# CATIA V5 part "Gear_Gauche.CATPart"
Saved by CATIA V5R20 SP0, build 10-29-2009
Part number: Pièce1
Bounding box of the stored display mesh (mm): x -14.825 to 18.25, y -12.496 to 12.496, z -18 to 15.7
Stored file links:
  C:\Users\Admin\Desktop\Gear Gauche.CATPart
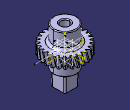
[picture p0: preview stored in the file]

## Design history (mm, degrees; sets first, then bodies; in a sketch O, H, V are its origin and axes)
Body1 (main body)
  Sketch1 on xy-plane, origin (0, 0, 0), H (1, 0, 0), V (0, 1, 0)
  Sketch2 on zx-plane, origin (0, 0, 0), H (-1, 0, 0), V (0, 0, 1)
    line L1 (0, 0) -> (1.2812, 4.4681)
    angle L1 V = 16
  Sketch3 on xy-plane, origin (0, 0, 0), H (1, 0, 0), V (0, 1, 0)
    circle A1 centre (0, 0) radius 10.75
    radius A1 = 10.75
  Pad1: profile Sketch3, direction (0, 0, 1), length 6.1
  Plane1: type Offset, RefPlane xy-plane, Offset 3.05
  Sketch4 on Plane1, origin (0, 0, 3.05), H (1, 0, 0), V (0, 1, 0)
    line L1 (0, 4.9753) -> (0, -6.0734)
    point P1 (0, 4.9753)
    line L2 (-14.8253, 0) -> (18.2495, 0)
    point P3 (-14.8253, 0)
    coincidence: P1 V, P3 H
    vertical: L1 V
    horizontal: L2 H
  Plane2: type Angle, RefPlane Plane1, Direction Sketch4.L2, Angle 15.6
  Sketch5 on Plane2, origin (0, -0.8097, 2.8239), H (1, 0, 0), V (0, 0.9632, 0.2689)
    point P1 (0, -9.9093)
    construction circle A1 centre (-0.013, 0.8407) radius 10.75
    construction line L1 through (0, 0.8407) direction (0, -1)
    construction line L2 through (0, 0.8407) direction (1, 0)
    point P2 (12.3622, 0.8407)
    axis line L3 (12.3622, 0.8407) -> (-13.4567, 0.8407)
    line L4 (12.437, 1.2157) -> (12.437, 0.4657)
    point P3 (10.737, 0.8407)
    point P4 (12.437, 1.2157)
    spline S1 through (12.437, 0.4657) (11.9519, 0.1717) (11.214, -0.0548) (10.6904, -0.1593)
    spline S2 through (12.437, 1.2157) (11.9519, 1.5097) (11.214, 1.7361) (10.6904, 1.8407)
    point P7 (10.6904, 1.8407)
    construction arc A2 centre (-0.013, 0.8407) radius 10.75 from (10.6904, -0.1593) to (10.6904, 1.8407) ccw
    reference projected line E1 (-14.8253, 0.8407) -> (18.2495, 0.8407) from Sketch4.L2
    reference projected line E2 (0, 5.6233) -> (0, -4.9974) from Sketch4.L1
    line L5 (10.6904, 1.8407) -> (9.804, 2.0177)
    point P10 (10.6904, 1.8407)
    line L6 (10.6904, -0.1593) -> (9.804, -0.3363)
    line L7 (9.804, 2.0177) -> (9.804, -0.3363)
    point P13 (12.437, 1.2157)
    point P14 (10.6904, 1.8407)
    point P15 (11.214, 1.7361)
    point P16 (11.214, -0.0548)
    distance P3 L4 = 1.7
    length L4 = 0.75
    radius A1 = 10.75
    coincidence: A1 P1, P1 L1, P2 L2, P3 A1, P3 L3, P14 P7, P4 P13, A2 A1, L3 E1, L1 E2, P14 P10, L5 P15, L6 P16
    vertical: L3 L2, L7 V
    horizontal: L4 L1
    symmetry: S2 S1 L3, P15 P16 L3
  Pad2: profile Sketch5, direction (0, -0.2689, 0.9632), up to end face of Pad1, opposite side up to start face of Pad1
  Sketch6 on yz-plane, origin (0, 0, 0), H (0, 1, 0), V (0, 0, 1)
    line L1 (0, 8.7327) -> (0, -6.8181)
    point P1 (0, 8.7327)
    coincidence: P1 V
    vertical: L1 V
  CircPattern1: of Pad2, instances 27, angular step 13.8462, axis from Sketch6.L1
  Sketch7 on face of CircPattern1, origin (0, 0, 6.1), H (1, 0, 0), V (0, 1, 0)
    circle A1 centre (0, 0) radius 7
    radius A1 = 7
  Pad3: profile Sketch7, direction (0, 0, 1), length 9.6
  Sketch8 on face of CircPattern1, origin (0, 0, 0), H (1, 0, 0), V (0, -1, 0)
    circle A1 centre (0, 0) radius 7
    radius A1 = 7
  Pad4: profile Sketch8, direction (0, 0, -1), length 8
  Sketch9 on end face of Pad4, origin (0, 0, -8), H (1, 0, 0), V (0, -1, 0)
    line L1 (-4.5, 4.5) -> (4.5, 4.5)
    line L2 (4.5, 4.5) -> (4.5, -4.5)
    line L3 (4.5, -4.5) -> (-4.5, -4.5)
    line L4 (-4.5, -4.5) -> (-4.5, 4.5)
    length L2 = 9
    length L3 = 9
    horizontal: L1 H, L3 H
    vertical: L2 V, L4 V
    symmetry: L2 L4 V, L1 L3 H
  Pad5: profile Sketch9, direction (0, 0, -1), length 10
  Sketch10 on yz-plane, origin (0, 0, 0), H (0, 1, 0), V (0, 0, 1)
    reference projected line E1 (7, -8) -> (-7, -8) from edge [face of Pad4 from Sketch8.A1 | end face of Pad4]
    reference projected line E4 (4.5, -18) -> (-4.5, -18) from edge [face of Pad5 from Sketch9.L2 | end face of Pad5]
    line L1 (-4.25, -18) -> (4.25, -18)
    point P9 (-4.25, -18)
    point P10 (4.25, -18)
    line L2 (-4.5, -8) -> (-4.25, -18)
    line L3 (4.5, -8) -> (4.25, -18)
    point P11 (-8.6782, -8)
    line L4 (-8.6782, -8) -> (-4.5, -8)
    line L5 (7.9099, -8) -> (7.9099, -20.4658)
    line L6 (7.9099, -20.4658) -> (-8.6782, -20.4658)
    line L7 (-8.6782, -20.4658) -> (-8.6782, -8)
    line L8 (4.5, -8) -> (7.9099, -8)
    length L1 = 8.5
    coincidence: P9 E4, P11 E1, L4 L8
    horizontal: L1 H, L4 H, L6 H, L8 H
    symmetry: P10 P9 V
    vertical: L5 V, L7 V
  Pocket1: profile Sketch10, direction (-1, 0, 0), length 10, mirrored extent
  Sketch11 on zx-plane, origin (0, 0, 0), H (-1, 0, 0), V (0, 0, 1)
    point P1 (-4.25, -18)
    line L1 (-4.25, -18) -> (4.25, -18)
    point P2 (4.25, -18)
    line L2 (-8.6782, -8) -> (-4.5, -8)
    line L3 (7.9099, -20.4658) -> (-8.6782, -20.4658)
    line L4 (7.9099, -8) -> (7.9099, -20.4658)
    line L5 (-8.6782, -20.4658) -> (-8.6782, -8)
    line L6 (4.5, -8) -> (7.9099, -8)
    projected line E1 (7, -8) -> (-7, -8) from edge [face of Pad4 from Sketch8.A1 | end face of Pad4]
    projected line E2 (-4.5, -8) -> (-4.5, -18) from edge [face of Pad5 from Sketch9.L2 | face of Pad5 from Sketch9.L3]
    projected line E3 (-4.5, -8) -> (-4.5, -18) from edge [face of Pad5 from Sketch9.L1 | face of Pad5 from Sketch9.L2]
    projected point E4 (-4.5, -18) from edge [face of Pad5 from Sketch9.L2 | end face of Pad5]
    line L7 (4.5, -8) -> (4.25, -18)
    line L8 (-4.5, -8) -> (-4.25, -18)
    length L1 = 8.5
    distance L1 L6 = 10
    horizontal: L1 H, L2 H, L3 H, L6 H
    symmetry: P2 P1 V
    vertical: L4 V, L5 V
    coincidence: L2 L6
  Pocket2: profile Sketch11, direction (0, -1, 0), length 10, mirrored extent
  Chamfer1: length 0.7, angle 45, on face of Pocket2 from Sketch11.L1
  Fillet1: radius 1, on edge [face of Pocket2 from Sketch11.L8 | face of Pocket1 from Sketch10.L3]; edge [face of Pocket1 from Sketch10.L2 | face of Pocket2 from Sketch11.L8]; edge [face of Pocket2 from Sketch11.L7 | face of Pocket1 from Sketch10.L2]; edge [face of Pocket1 from Sketch10.L3 | face of Pocket2 from Sketch11.L7]; edge [face of Chamfer1 | face of Chamfer1] (x4)
  Fillet2: radius 0.5, on face of Pocket2
  Fillet3: radius 0.5, on edge [face of Pad3 from Sketch7.A1 | end face of Pad3]
  Sketch12 on end face of Pad3, origin (0, 0, 15.7), H (1, 0, 0), V (0, 1, 0)
    circle A1 centre (0, 0) radius 2.7
    radius A1 = 2.7
  Pocket3: profile Sketch12, direction (0, 0, -1), through (limit type 3)
  Fillet4: radius 0.5, on face of Pocket3 from Sketch12.A1
  Fillet5: radius 1.5, on edge [face of CircPattern1 | face of Pad4 from Sketch8.A1]; edge [face of CircPattern1 | face of Pad3 from Sketch7.A1]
